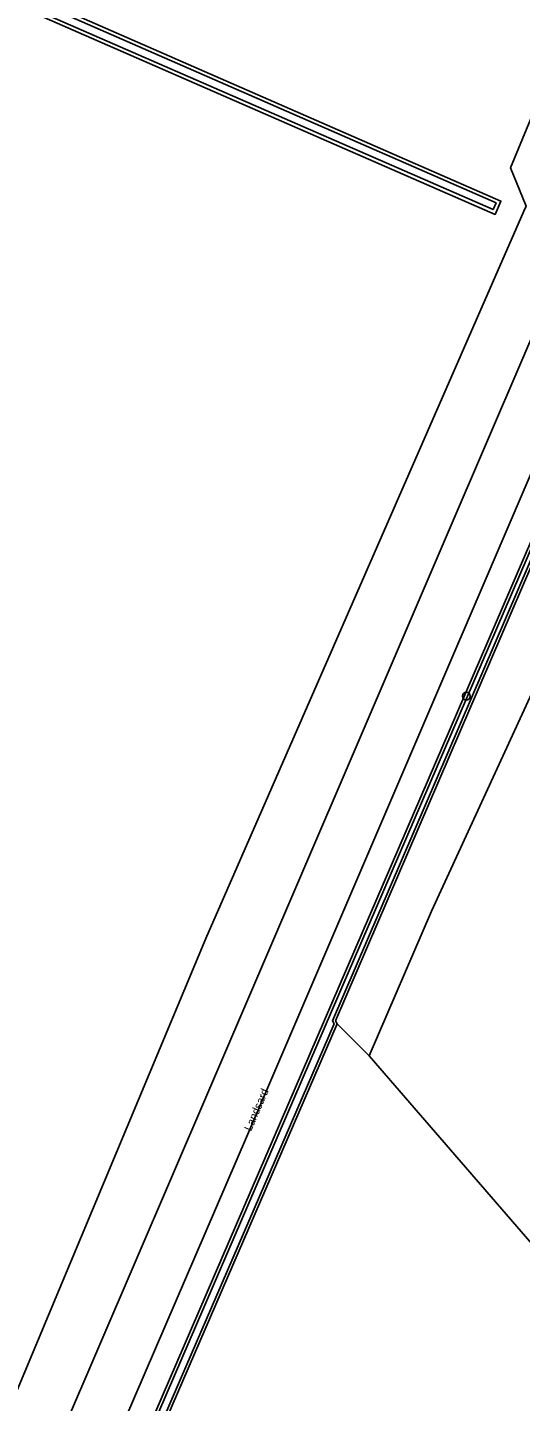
# Model space of a CAD drawing. Extents: x 155209 to 156823, y 385356 to 388482.
# Drawn here: x 155937 to 155998.6, y 386038.3 to 386210 of the extents above; entities that cross this region are included whole.
import ezdxf

# ---------------------------------------------------------------- set-up
doc = ezdxf.new("R2010")
doc.units = 0
for name, color, linetype in [('IMGEO_Berm_groen', 7, 'Continuous'), ('IMGEO_Boom', 7, 'Continuous'), ('IMGEO_Hek', 7, 'Continuous'), ('IMGEO_Loofbos', 7, 'Continuous'), ('IMGEO_Naaldbos', 7, 'Continuous'), ('IMGEO_Openbare_ruimte_label', 7, 'Continuous'), ('IMGEO_Rijbaan_lokaal_gesloten', 7, 'Continuous'), ('IMGEO_Waterloop', 7, 'Continuous')]:
    doc.layers.add(name, color=color, linetype=linetype)

msp = doc.modelspace()

# ---------------------------------------------------------------- linework, layer by layer
at = {"layer": 'IMGEO_Berm_groen'}
for points in [[(155916.98, 385994.93), (155959.3, 386096.17), (155999.02, 386187.05), (155999.28, 386187.65), (155997.34, 386192.47), (156017.72, 386241.8), (156020.33, 386248.12)], [(156013.5, 386177.7), (156000, 386146), (155952.02, 386034.68)]]:
    msp.add_lwpolyline(points, dxfattribs=at)
at = {"layer": 'IMGEO_Boom'}
msp.add_circle((155991.83, 386126.43), 0.489, dxfattribs=at)
at = {"layer": 'IMGEO_Hek'}
for points in [[(155979.68, 386081.47), (155987.48, 386099.58), (156000, 386126.8), (156006.74, 386141.43), (156000.68, 386144.39)], [(156001.7, 386056.03), (156000, 386057.99), (155979.68, 386081.47)]]:
    msp.add_lwpolyline(points, dxfattribs=at)
at = {"layer": 'IMGEO_Loofbos'}
msp.add_lwpolyline([(155822.24, 386038.89), (155827.56, 386049.39), (155854.18, 386100.13), (155871.23, 386133.09), (155899.02, 386188.41), (155914.94, 386221.5), (155915.31, 386221.64), (155995.42, 386186.63), (155996.15, 386188.3), (155914.38, 386224.1), (155912.74, 386224.24), (155875.07, 386241.03), (155857.11, 386250), (155838.57, 386259.27), (155825.81, 386265.2)], dxfattribs=at)
at = {"layer": 'IMGEO_Naaldbos'}
for points in [[(156000.68, 386144.39), (156000, 386142.83), (155975.49, 386085.88), (155975.71, 386085.5)], [(156000.68, 386144.39), (156006.74, 386141.43), (156000, 386126.8), (155987.48, 386099.58), (155979.68, 386081.47)], [(155942.72, 386009.19), (155975.71, 386085.5)], [(155975.71, 386085.5), (155979.68, 386081.47)], [(155979.68, 386081.47), (156000, 386057.99), (156001.7, 386056.03)]]:
    msp.add_lwpolyline(points, dxfattribs=at)
at = {"layer": 'IMGEO_Rijbaan_lokaal_gesloten'}
for points in [[(156003.54, 386179.53), (155989.7, 386147.22), (155959.53, 386076.88), (155927.74, 386002.82)], [(155949.14, 386035.92), (155965.64, 386074.34), (155984.91, 386119.23), (156009.58, 386176.82)]]:
    msp.add_lwpolyline(points, dxfattribs=at)
at = {"layer": 'IMGEO_Waterloop'}
for points in [[(155825.61, 386264.79), (155838.37, 386258.86), (155856.91, 386249.6), (155874.87, 386240.62), (155912.62, 386223.8), (155914.26, 386223.65), (155995.54, 386188.08), (155995.17, 386187.24), (155915.32, 386222.13), (155914.61, 386221.86), (155898.62, 386188.61), (155870.82, 386133.3), (155853.78, 386100.34), (155827.16, 386049.6), (155821.83, 386039.09)], [(156015.54, 386179.18), (156015.76, 386179.19), (156015.84, 386179.15), (156015.91, 386178.56), (156028.73, 386169.96), (156048.81, 386156.86), (156048.58, 386156.51), (156048.41, 386156.24), (156033.05, 386166.23), (156015.52, 386177.85), (156015.03, 386177.92), (156014.67, 386177.6), (156000.35, 386144.53), (155999.67, 386142.97), (155975.09, 386085.85), (155975.31, 386085.48), (155942.79, 386010.26)], [(155942.79, 386010.26), (155942.16, 386010.92), (156000.33, 386145.86), (156013.83, 386177.55)]]:
    msp.add_lwpolyline(points, dxfattribs=at)

# ---------------------------------------------------------------- texts
at = {"layer": 'IMGEO_Openbare_ruimte_label'}
msp.add_text('Landsard', height=1, rotation=66.666, dxfattribs=at).set_placement((155964.95, 386072))

doc.saveas('drawing.dxf')
